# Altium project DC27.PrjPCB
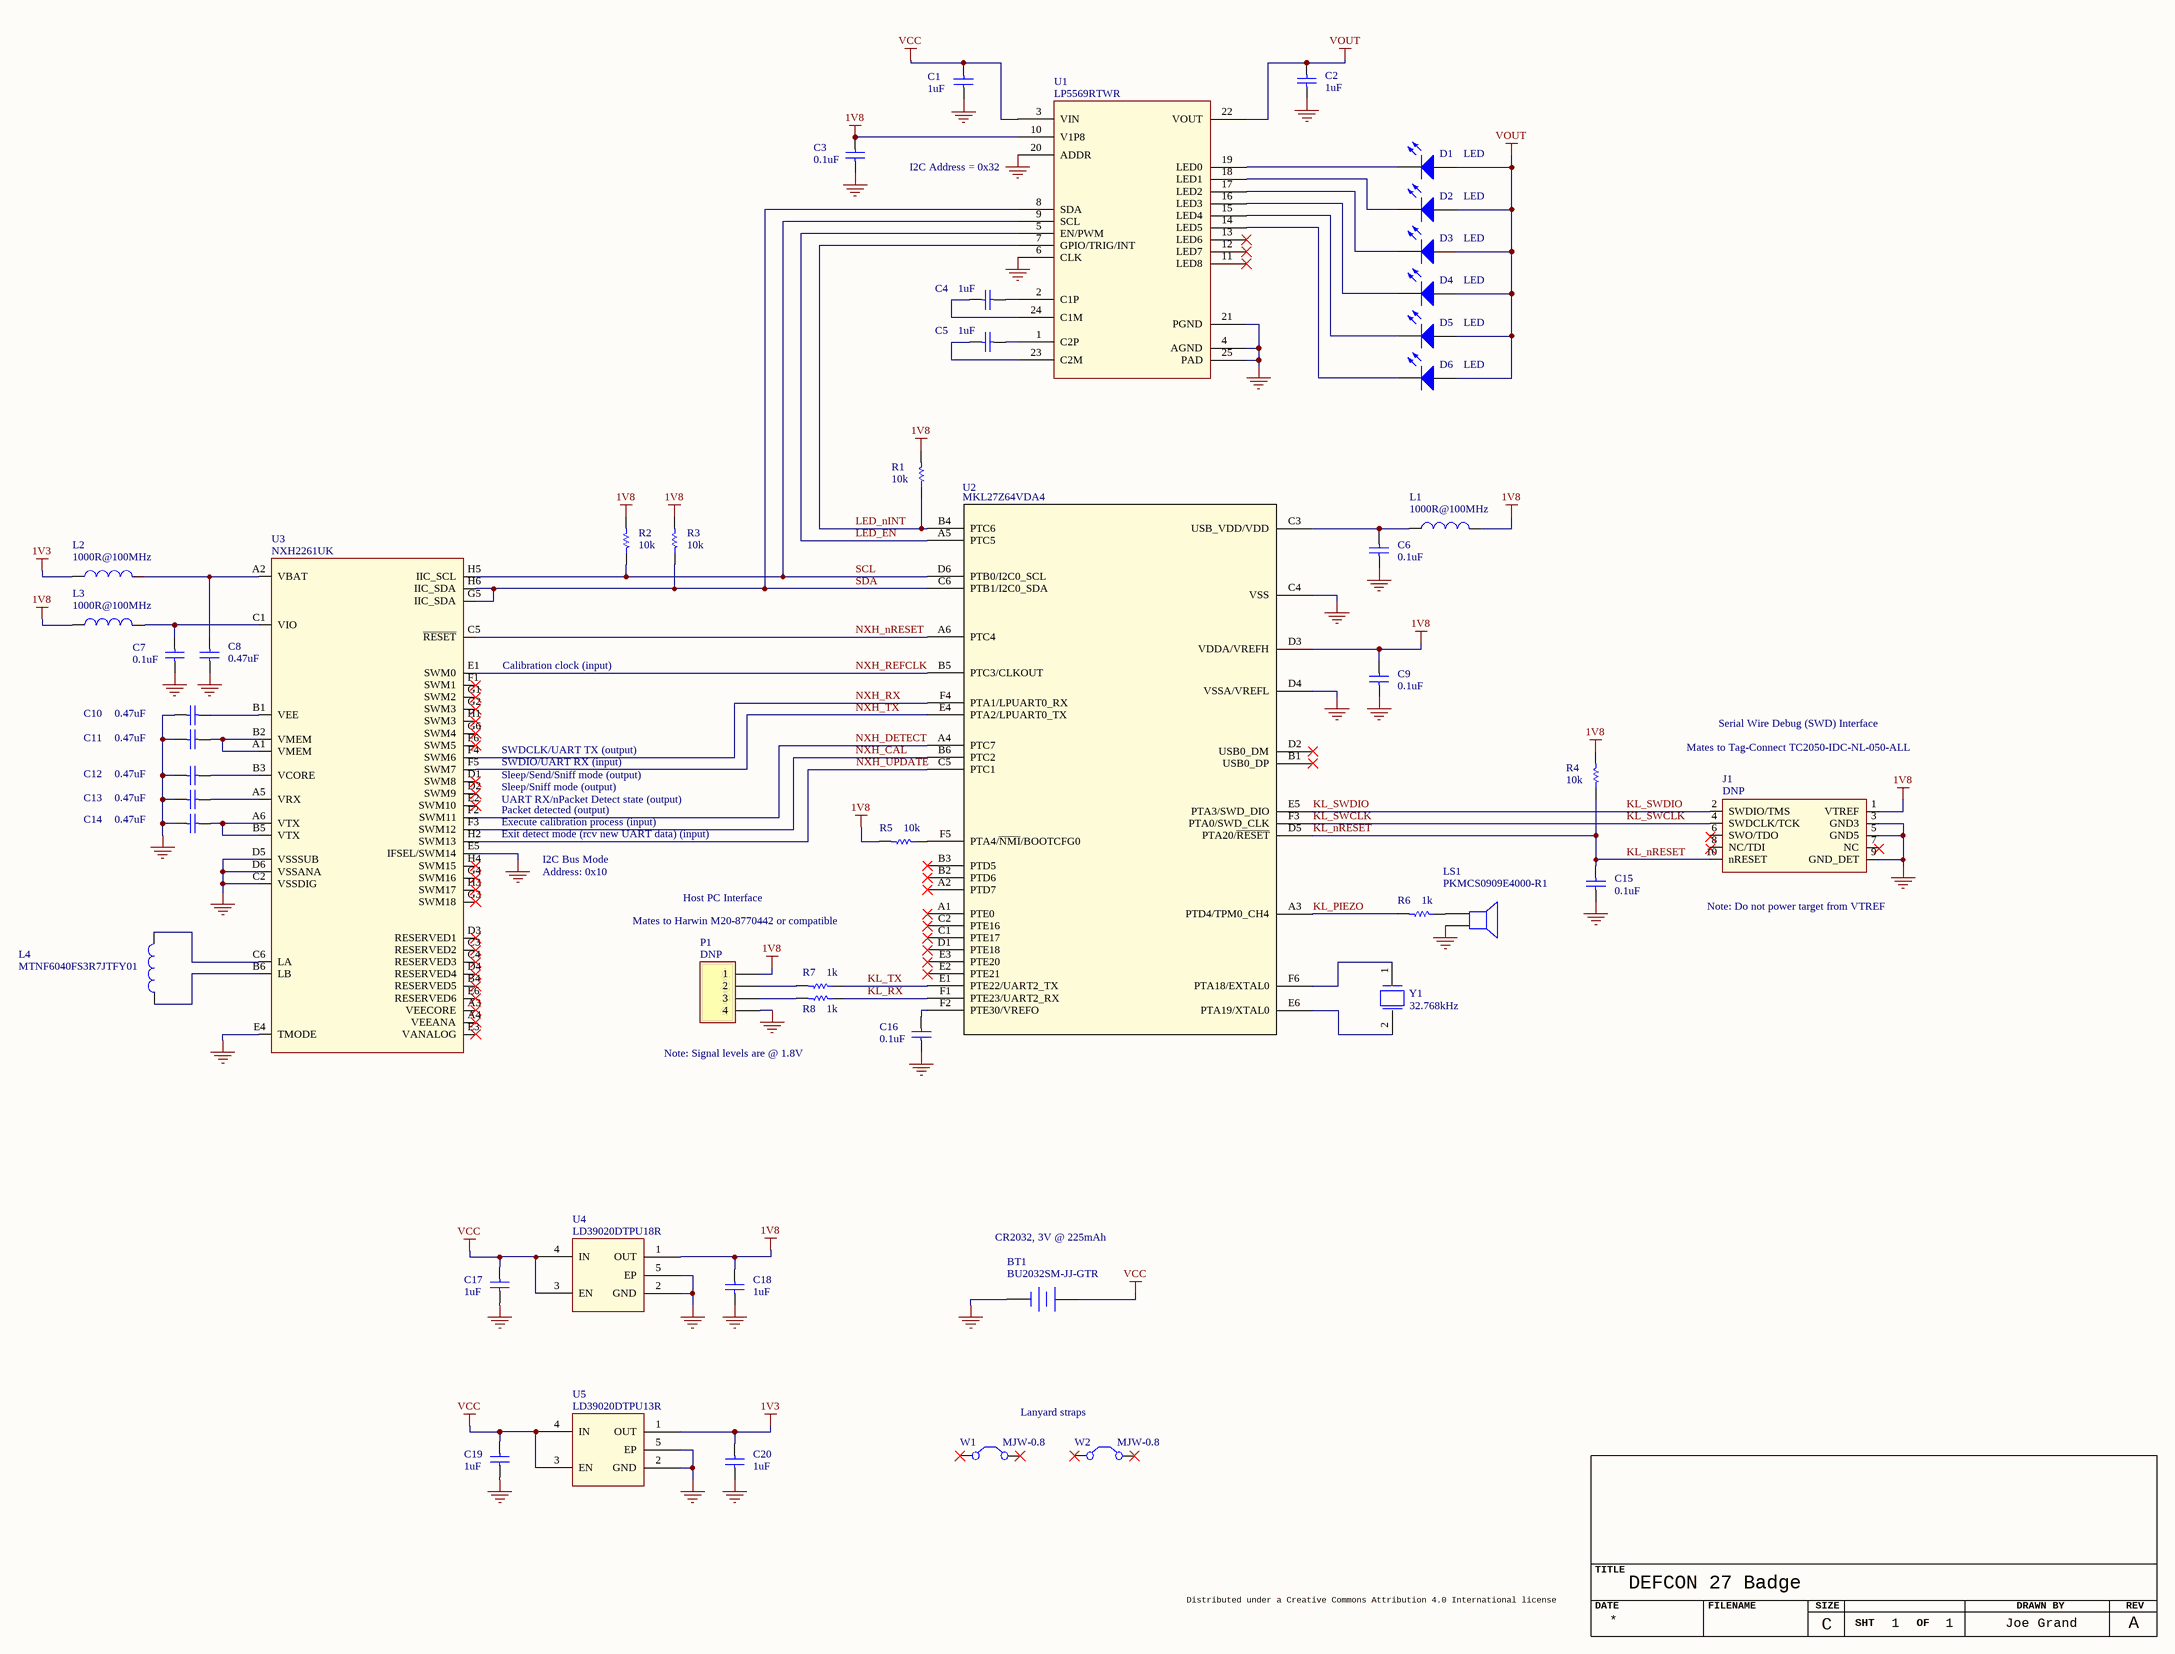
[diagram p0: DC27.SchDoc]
1 sheet, 51 parts. Net scope: global (net labels, ports and power ports of the same name join across sheets).
Board file: DC27.PcbDoc

## Sheet DC27.SchDoc: DEFCON 27 Badge
size C; Engineer: Joe Grand; Revision: A; SheetNumber: 1; SheetTotal: 1; PageSetup: Record=PageOptions¦CenterHorizontal=True¦CenterVertical=True¦PrintScale=0.70¦XCorrection=1.00¦YCorrection=1.00¦PrintKind=0¦BorderSize=5000000¦LeftOffset=0¦BottomOffset=0¦Orientation=2¦PaperLength=1000¦PaperWidth=1000¦Scale=100¦PaperSource=7¦PrintQuality=-4¦MediaType=1¦DitherType=10¦PrintScaleMode=1¦PaperKind=Letter

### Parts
*  Page Size: C  RevCode: A  Page Count: 1  OrgName: Joe Grand  Title: DEFCON 27 Badge  (hidden comment: GIS Title Block)  (graphical)
BT1  BU2032SM-JJ-GTR  [BU2032SM]
C1  value 1uF  [CAPC1005N]  (hidden comment: Cap)
C2  value 1uF  [CAPC1005N]  (hidden comment: Cap)
C3  value 0.1uF  [CAPC1005N]  (hidden comment: Cap)
C4  value 1uF  [CAPC1005N]  (hidden comment: Cap)
C5  value 1uF  [CAPC1005N]  (hidden comment: Cap)
C6  value 0.1uF  [CAPC1005N]  (hidden comment: Cap)
C7  value 0.1uF  [CAPC1005N]  (hidden comment: Cap)
C8  value 0.47uF  [RESC0603N]  (hidden comment: Cap)
C9  value 0.1uF  [CAPC1005N]  (hidden comment: Cap)
C10  value 0.47uF  [RESC0603N]  (hidden comment: Cap)
C11  value 0.47uF  [RESC0603N]  (hidden comment: Cap)
C12  value 0.47uF  [RESC0603N]  (hidden comment: Cap)
C13  value 0.47uF  [RESC0603N]  (hidden comment: Cap)
C14  value 0.47uF  [RESC0603N]  (hidden comment: Cap)
C15  value 0.1uF  [CAPC1005N]  (hidden comment: Cap)
C16  value 0.1uF  [CAPC1005N]  (hidden comment: Cap)
C17  value 1uF  [CAPC1005N]  (hidden comment: Cap)
C18  value 1uF  [CAPC1005N]  (hidden comment: Cap)
C19  value 1uF  [CAPC1005N]  (hidden comment: Cap)
C20  value 1uF  [CAPC1005N]  (hidden comment: Cap)
D1  LED  [APTR3216]
D2  LED  [APTR3216]
D3  LED  [APTR3216]
D4  LED  [APTR3216]
D5  LED  [APTR3216]
D6  LED  [APTR3216]
J1  DNP  [TC2050-IDC-NL-FP]
L1  value 1000R@100MHz  [INDC1608N]  (hidden comment: Inductor)
L2  value 1000R@100MHz  [INDC1608N]  (hidden comment: Inductor)
L3  value 1000R@100MHz  [INDC1608N]  (hidden comment: Inductor)
L4  value MTNF6040FS3R7JTFY01  [INDC6040]  (hidden comment: Inductor)
LS1  PKMCS0909E4000-R1  [PKMCS0909E4000]
P1  DNP  [HEADER4 - SMD]
R1  value 10k  [RESC1005N]  (hidden comment: Res1)
R2  value 10k  [RESC1005N]  (hidden comment: Res1)
R3  value 10k  [RESC1005N]  (hidden comment: Res1)
R4  value 10k  [RESC1005N]  (hidden comment: Res1)
R5  value 10k  [RESC1005N]  (hidden comment: Res1)
R6  value 1k  [RESC1005N]  (hidden comment: Res1)
R7  value 1k  [RESC1005N]  (hidden comment: Res1)
R8  value 1k  [RESC1005N]  (hidden comment: Res1)
U1  LP5569RTWR  [VQFN50P400X400X100-24N]
U2  MKL27Z64VDA4  [SOT1558-1]
U3  NXH2261UK  [SOT1887_NXP]
U4  LD39020DTPU18R  [VREG_LD39020DTPU33R]
U5  LD39020DTPU13R  [VREG_LD39020DTPU33R]
W1  MJW-0.8  [MJW-0.8-WITH-VIAS]
W2  MJW-0.8  [MJW-0.8-WITH-VIAS]
Y1  value 32.768kHz  [ABS07]  (hidden comment: XTL_HC49-4H)

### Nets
1V3: C20.2 L2.2 U5.1(OUT)
1V8: C3.2 C9.2 C18.2 J1.1(VTREF) L1.1 L3.2 P1.1 R1.2 R2.2 R3.2 R4.2 R5.2 U1.10(V1P8) U2.D3(VDDA/VREFH) U4.1(OUT)
GND: BT1.2(-) C1.1 C2.1 C3.1 C6.1 C7.1 C8.2 C9.1 C10.2 C11.2 C12.2 C13.2 C14.2 C15.1 C16.1 C17.1 C18.1 C19.1 C20.1 J1.3(GND3) J1.5(GND5) J1.9(GND_DET) LS1.2 P1.4 U1.4(AGND) U1.6(CLK) U1.20(ADDR) U1.21(PGND) U1.25(PAD) U2.C4(VSS) U2.D4(VSSA/VREFL) U3.C2(VSSDIG) U3.D5(VSSSUB) U3.D6(VSSANA) U3.E4(TMODE) U3.E5(IFSEL/SWM14) U4.2(GND) U4.5(EP) U5.2(GND) U5.5(EP)
VCC: BT1.1(+) C1.2 C17.2 C19.2 U1.3(VIN) U4.3(EN) U4.4(IN) U5.3(EN) U5.4(IN)
VOUT: C2.2 D1.1(A) D2.1(A) D3.1(A) D4.1(A) D5.1(A) D6.1(A) U1.22(VOUT)
KL_nRESET: C15.2 J1.10(nRESET) R4.1 U2.D5(PTA20/~{RESET})
KL_PIEZO: R6.2 U2.A3(PTD4/TPM0_CH4)
KL_RX: R8.1 U2.F1(PTE23/UART2_RX)
KL_SWCLK: J1.4(SWDCLK/TCK) U2.F3(PTA0/SWD_CLK)
KL_SWDIO: J1.2(SWDIO/TMS) U2.E5(PTA3/SWD_DIO)
KL_TX: R7.1 U2.E1(PTE22/UART2_TX)
LED_EN: U1.5(EN/PWM) U2.A5(PTC5)
LED_nINT: R1.1 U1.7(GPIO/TRIG/INT) U2.B4(PTC6)
NXH_CAL: U2.B6(PTC2) U3.F3(SWM12)
NXH_DETECT: U2.A4(PTC7) U3.F2(SWM11)
NXH_nRESET: U2.A6(PTC4) U3.C5(~{RESET})
NXH_REFCLK: U2.B5(PTC3/CLKOUT) U3.E1(SWM0)
NXH_RX: U2.F4(PTA1/LPUART0_RX) U3.F4(SWM6)
NXH_TX: U2.E4(PTA2/LPUART0_TX) U3.F5(SWM7)
NXH_UPDATE: U2.C5(PTC1) U3.H2(SWM13)
SCL: R2.1 U1.9(SCL) U2.D6(PTB0/I2C0_SCL) U3.H5(IIC_SCL)
SDA: R3.1 U1.8(SDA) U2.C6(PTB1/I2C0_SDA) U3.G5(IIC_SDA) U3.H6(IIC_SDA)
NetC4_1: C4.1 U1.2(C1P)
NetC4_2: C4.2 U1.24(C1M)
NetC5_1: C5.1 U1.1(C2P)
NetC5_2: C5.2 U1.23(C2M)
NetC6_2: C6.2 L1.2 U2.C3(USB_VDD/VDD)
NetC7_2: C7.2 L3.1 U3.C1(VIO)
NetC8_1: C8.1 L2.1 U3.A2(VBAT)
NetC10_1: C10.1 U3.B1(VEE)
NetC11_1: C11.1 U3.A1(VMEM) U3.B2(VMEM)
NetC12_1: C12.1 U3.B3(VCORE)
NetC13_1: C13.1 U3.A5(VRX)
NetC14_1: C14.1 U3.A6(VTX) U3.B5(VTX)
NetC16_2: C16.2 U2.F2(PTE30/VREFO)
NetD1_2: D1.2(K) U1.19(LED0)
NetD2_2: D2.2(K) U1.18(LED1)
NetD3_2: D3.2(K) U1.17(LED2)
NetD4_2: D4.2(K) U1.16(LED3)
NetD5_2: D5.2(K) U1.15(LED4)
NetD6_2: D6.2(K) U1.14(LED5)
NetL4_1: L4.1 U3.C6(LA)
NetL4_2: L4.2 U3.B6(LB)
NetLS1_1: LS1.1 R6.1
NetP1_2: P1.2 R7.2
NetP1_3: P1.3 R8.2
NetR5_1: R5.1 U2.F5(PTA4/~{NMI}/BOOTCFG0)
NetU2_E6: U2.E6(PTA19/XTAL0) Y1.2
NetU2_F6: U2.F6(PTA18/EXTAL0) Y1.1

Not connected (* = marked no-connect by the designer): J1 6(SWO/TDO) 7(NC) 8(NC/TDI); U1 11(LED8)* 12(LED7)* 13(LED6)*; U2 A1(PTE0)* A2(PTD7)* B1(USB0_DP)* B2(PTD6)* B3(PTD5)* C1(PTE17)* C2(PTE16)* D1(PTE18)* D2(USB0_DM)* E2(PTE21)* E3(PTE20)*; U3 A3(VEECORE)* A4(VEEANA)* B4(RESERVED5)* C3(RESERVED2)* C4(RESERVED3)* D1(SWM8)* D2(SWM9)* D3(RESERVED1)* D4(RESERVED4)* E2(SWM10)* E3(VANALOG)* E6(RESERVED6)* F1(SWM1)* F6(SWM5)* G1(SWM2)* G2(SWM3)* G3(SWM18)* G4(SWM16)* G6(SWM4)* H1(SWM3)* H3(SWM17)* H4(SWM15)*; W1 1(C1)* 2(C2)*; W2 1(C1)* 2(C2)*

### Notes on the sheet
- I2C Address = 0x32
- (near U3) Calibration clock (input)
- Serial Wire Debug (SWD) Interface
- (near U3) SWDCLK/UART TX (output)
- (near U3) SWDIO/UART RX (input)
- (near U3) Sleep/Sniff mode (output)
- (near U3) Sleep/Send/Sniff mode (output)
- Mates to Tag-Connect TC2050-IDC-NL-050-ALL
- (near U3) Exit detect mode (rcv new UART data) (input)
- (near U3) Execute calibration process (input)
- (near U3) Packet detected (output)
- (near U3) UART RX/nPacket Detect state (output)
- I2C Bus Mode
- Address: 0x10
- Host PC Interface
- (near J1) Note: Do not power target from VTREF
- Mates to Harwin M20-8770442 or compatible
- Note: Signal levels are @ 1.8V
- CR2032, 3V @ 225mAh
- Lanyard straps
- Distributed under a Creative Commons Attribution 4.0 International license

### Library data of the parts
BT1 = Battery: Single Cell Battery Holder
C1 C2 C4 C5 C17-C20 = Cap: CL05A105KP5NNNC
C3 C6 C7 C9 C15 C16 = Cap: C0402C104K8PAC
C8 C10-C14 = Cap: Taiyo Yuden AMK063BJ474MP-F
D1-D6 = LED: Kingbright APTR
J1 = ARM_SWD_10: TC2050-IDC-NL-050-ALL
L1-L3 = Inductor: BLM18RK102SN1D
LS1 = Speaker: Loudspeaker
P1 = Header 4: Header, 4-Pin
R1-R8 = Res1: Resistor
U1 = LP5569: TI I2C 9-channel LED Driver
U2 = MKL27Z64VDA4: Vendor: NXP
U3 = NXH2261: NXP NFMI
U4 U5 = LD30920: ST Low-Dropout Linear Regulator (DFN1x1-4L)
W1 W2 = Jumper: Jumper Wire
Y1 = XTL_HC49-4H: Abracon ABS07-32.768KHZ-1-T; Part Number: Digikey HC49US30.000MAJB-ND; Manufacturer #1: Citizen; Manuf Part No: HC49US30.000MAJB; Geometry.Height: 3.5mm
